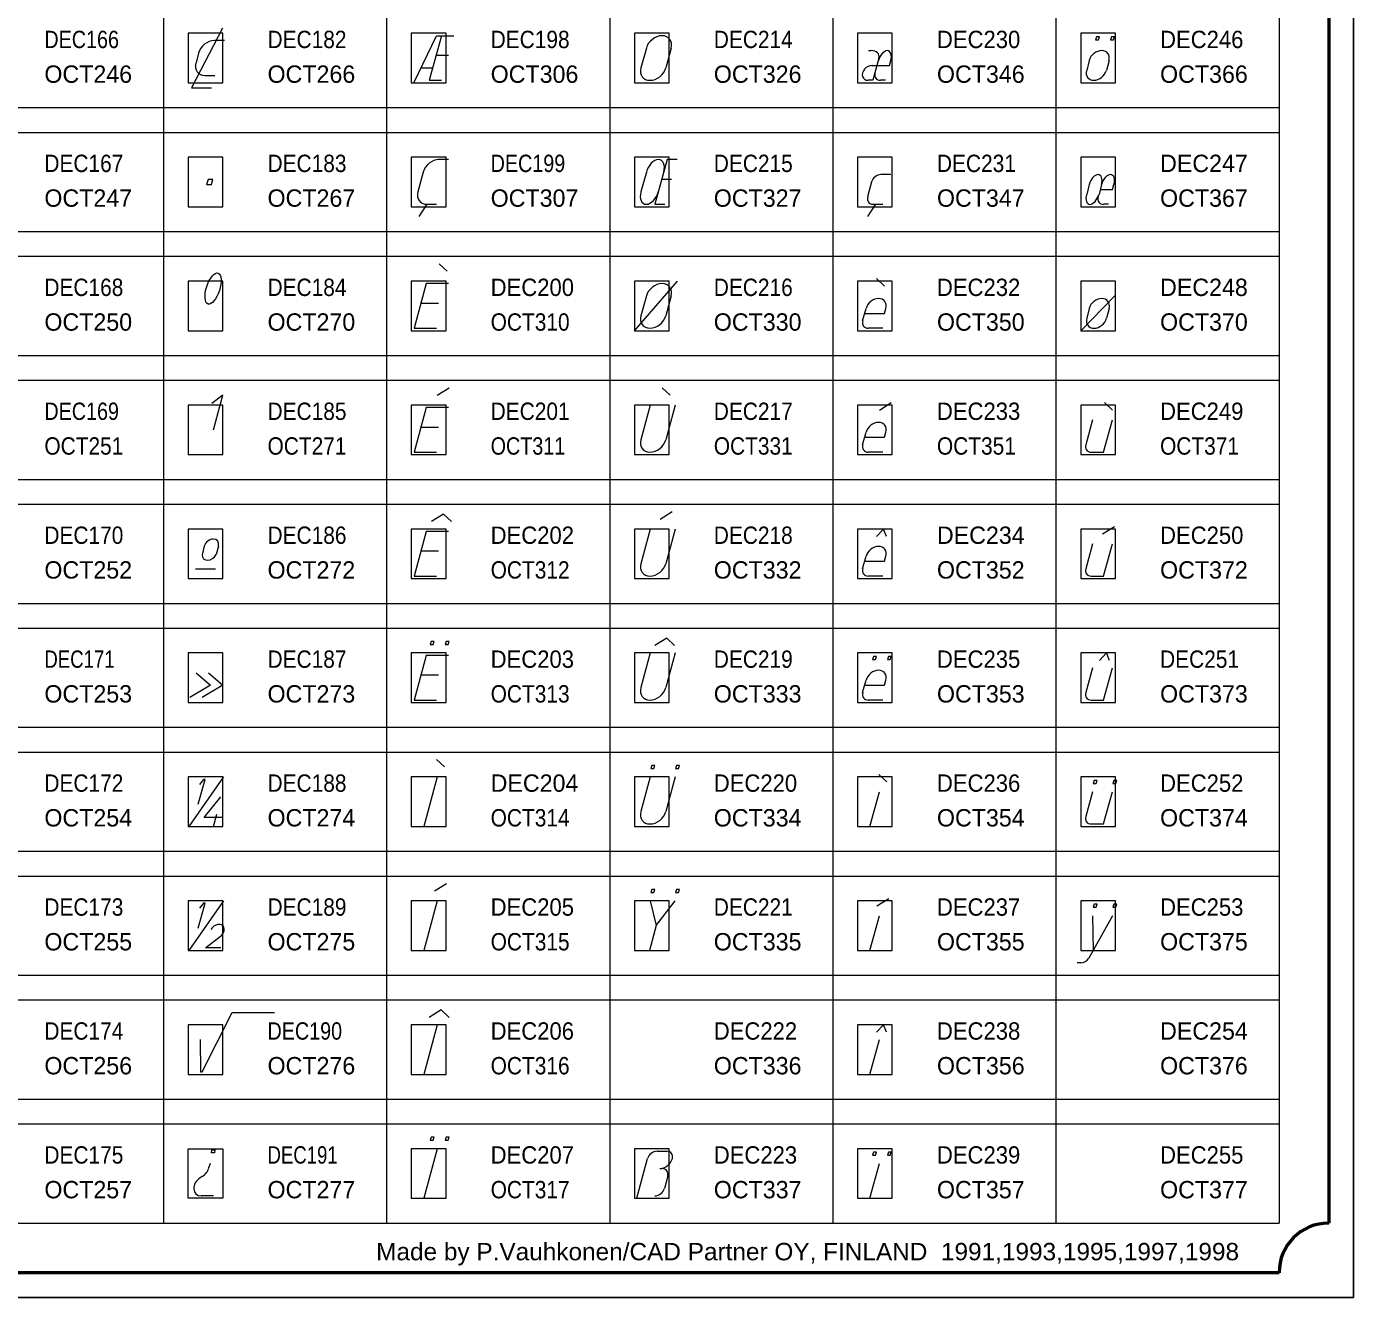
# Model space of a CAD drawing. Extents: x -200 to 7300, y -200 to 4800.
# Drawn here: x 4624 to 7300, y -200 to 2364 of the extents above; entities that cross this region are included whole.
import ezdxf
from ezdxf.enums import TextEntityAlignment as Align

# ---------------------------------------------------------------- set-up
doc = ezdxf.new("R2010")
doc.units = 0
doc.header["$LTSCALE"] = 14
for name, color, linetype, lineweight in [('1', 7, 'Continuous', 13), ('5', 7, 'Continuous', 40), ('6', 7, 'Continuous', 13), ('63', 7, 'Continuous', 13)]:
    doc.layers.add(name, color=color, linetype=linetype, lineweight=lineweight)
doc.layers.add('10', color=7, linetype='Continuous')
doc.layers.add('11', color=7, linetype='Continuous')

msp = doc.modelspace()

# ---------------------------------------------------------------- linework, layer by layer
at = {"layer": '1'}
for p, q in [((5023, 2335), (5003, 2335)), ((4971, 2310), (4966, 2290)), ((5475, 2305), (5450, 2305)), ((5874, 2320), (5863, 2280)), ((5924, 2320), (5913, 2280)), ((6322, 2315), (6327, 2315)), ((5419, 2280), (5443, 2280)), ((6329, 2285), (6339, 2285)), ((6767, 2295), (6762, 2275)), ((6807, 2295), (6802, 2275)), ((4984, 2265), (5004, 2265)), ((6356, 2255), (6346, 2255)), ((5475, 2095), (5455, 2095)), ((5424, 2070), (5413, 2030)), ((5874, 2070), (5863, 2030)), ((6367, 2065), (6347, 2065)), ((5925, 2055), (5905, 2055)), ((6328, 2050), (6320, 2020)), ((6767, 2045), (6762, 2025)), ((6792, 2045), (6787, 2025)), ((5431, 2005), (5415, 1980)), ((5431, 2005), (5451, 2005)), ((6336, 2005), (6320, 1980)), ((6331, 2005), (6351, 2005)), ((6806, 2005), (6796, 2005)), ((5472, 1870), (5456, 1885)), ((5850, 1750), (5937, 1850)), ((6354, 1840), (6338, 1855)), ((5874, 1820), (5863, 1780)), ((5924, 1820), (5913, 1780)), ((6819, 1820), (6750, 1750)), ((5455, 1805), (5420, 1805)), ((6310, 1770), (6317, 1795)), ((6767, 1795), (6762, 1775)), ((6807, 1795), (6802, 1775)), ((6351, 1755), (6321, 1755)), ((5452, 1620), (5476, 1635)), ((5922, 1620), (5906, 1635)), ((5882, 1600), (5863, 1530)), ((5932, 1600), (5913, 1530)), ((6344, 1590), (6368, 1605)), ((6814, 1590), (6798, 1605)), ((5455, 1555), (5420, 1555)), ((6774, 1570), (6760, 1520)), ((6310, 1520), (6317, 1545)), ((6351, 1505), (6321, 1505)), ((5902, 1370), (5926, 1385)), ((5882, 1350), (5863, 1280)), ((5932, 1350), (5913, 1280)), ((6794, 1340), (6818, 1355)), ((4982.5, 1315.4), (4978.2, 1298.2)), ((5011.1, 1315.4), (5006.3, 1298.5)), ((6774, 1320), (6760, 1270)), ((5455, 1305), (5420, 1305)), ((6310, 1270), (6317, 1295)), ((4965, 1270), (5005, 1270)), ((6351, 1255), (6321, 1255)), ((5882, 1100), (5863, 1030)), ((5932, 1100), (5913, 1030)), ((5455, 1055), (5420, 1055)), ((6310, 1020), (6317, 1045)), ((6774, 1070), (6760, 1020)), ((6351, 1005), (6321, 1005)), ((5467, 870), (5451, 885)), ((4952, 750), (5022, 850)), ((5452, 850), (5425, 750)), ((5882, 850), (5863, 780)), ((5932, 850), (5913, 780)), ((6359, 840), (6343, 855)), ((6325, 750), (6344, 820)), ((6774, 820), (6760, 770)), ((5001, 750), (5008, 775)), ((5447, 620), (5471, 635)), ((4952, 500), (5022, 600)), ((5452, 600), (5425, 500)), ((6339, 590), (6363, 605)), ((6325, 500), (6344, 570)), ((6814, 570), (6766.5, 484.5)), ((6774, 570), (6775, 500)), ((5894, 550), (5880, 500)), ((6750, 475), (6743, 475)), ((5452, 350), (5425, 250)), ((6325, 250), (6344, 320)), ((5452, 100), (5425, 0)), ((5896, 95), (5916, 95)), ((4994, 70), (4991, 61)), ((5855, 0), (5876.5, 80)), ((5901.1, 60), (5906.1, 60)), ((6325, 0), (6344, 70)), ((4978, 44), (4974, 41)), ((5917, 45), (5910.4, 20)), ((5001, 5), (4976, 5))]:
    msp.add_line(p, q, dxfattribs=at)
for points in [[(5019, 2360), (4957, 2240), (4997, 2240)], [(5405, 2250), (5451, 2345), (5486, 2345)], [(5461, 2345), (5436, 2255), (5461, 2255)], [(6343, 2300), (6331, 2255), (6321, 2255)], [(6339, 2285), (6364, 2285), (6367, 2295)], [(5936, 2095), (5916, 2095), (5891, 2005), (5911, 2005)], [(6789, 2035), (6814, 2035), (6817, 2045)], [(5475, 1845), (5430, 1845), (5406, 1755), (5451, 1755)], [(6314, 1785), (6354, 1785), (6357, 1795)], [(5001, 1550), (5020, 1620), (4998, 1603)], [(5475, 1595), (5430, 1595), (5406, 1505), (5451, 1505)], [(6771, 1505), (6796, 1505), (6814, 1570)], [(6314, 1535), (6354, 1535), (6357, 1545)], [(5481, 1365), (5465, 1380), (5441, 1365)], [(5475, 1345), (5430, 1345), (5406, 1255), (5451, 1255)], [(6358, 1335), (6352, 1350), (6338, 1335)], [(6771, 1255), (6796, 1255), (6814, 1320)], [(6314, 1285), (6354, 1285), (6357, 1295)], [(5931, 1115), (5915, 1130), (5891, 1115)], [(6808, 1085), (6802, 1100), (6788, 1085)], [(5475, 1095), (5430, 1095), (5406, 1005), (5451, 1005)], [(4966, 1060), (4995, 1035), (4953, 1010)], [(4991, 1060), (5020, 1035), (4978, 1010)], [(6314, 1035), (6354, 1035), (6357, 1045)], [(6771, 1005), (6796, 1005), (6814, 1070)], [(4970, 795), (4984, 845), (4981, 845), (4973, 835)], [(5020, 768), (4982, 768), (5016, 810)], [(6771, 755), (6796, 755), (6814, 820)], [(4970, 545), (4984, 595), (4981, 595), (4973, 585)], [(5882, 600), (5894, 550), (5932, 600)], [(5016, 505), (4985, 505), (5018, 531)], [(4974, 320), (4975, 255), (4978, 255), (5039, 375), (5124, 375)], [(5476, 365), (5460, 380), (5436, 365)], [(6358, 335), (6352, 350), (6338, 335)]]:
    msp.add_lwpolyline(points, dxfattribs=at)
for points in [[(6780, 2337), (6786, 2337), (6788, 2343), (6782, 2343)], [(6810, 2337), (6816, 2337), (6818, 2343), (6812, 2343)], [(4987, 2045), (4997, 2045), (5000, 2055), (4990, 2055)], [(5438, 1117), (5444, 1117), (5446, 1123), (5440, 1123)], [(5468, 1117), (5474, 1117), (5476, 1123), (5470, 1123)], [(6330, 1087), (6336, 1087), (6338, 1093), (6332, 1093)], [(6360, 1087), (6366, 1087), (6368, 1093), (6362, 1093)], [(5883, 867), (5889, 867), (5891, 873), (5885, 873)], [(5933, 867), (5939, 867), (5941, 873), (5935, 873)], [(6775, 837), (6781, 837), (6783, 843), (6777, 843)], [(6815, 837), (6821, 837), (6823, 843), (6817, 843)], [(5883, 617), (5889, 617), (5891, 623), (5885, 623)], [(5933, 617), (5939, 617), (5941, 623), (5935, 623)], [(6775, 587), (6781, 587), (6783, 593), (6777, 593)], [(6815, 587), (6821, 587), (6823, 593), (6817, 593)], [(5438, 117), (5444, 117), (5446, 123), (5440, 123)], [(5468, 117), (5474, 117), (5476, 123), (5470, 123)], [(5003, 92), (4997, 92), (4998, 98), (5004, 98)], [(6330, 87), (6336, 87), (6338, 93), (6332, 93)], [(6360, 87), (6366, 87), (6368, 93), (6362, 93)]]:
    msp.add_lwpolyline(points, close=True, dxfattribs=at)
for centre, major_axis, ratio, start_param, end_param in [((4995.99, 2310), (-21.5, -18.81), 0.765566, 3.860429, 5.4312252), ((5899, 2320), (-21.5, -18.81), 0.765566, 2.2896326, 5.4312252), ((6323, 2300), (20.01, 5.84), 0.690505, 5.8830717, 7.453868), ((6354.45, 2294.85), (-8.15, -19.47), 0.561107, 1.8015141, 4.9431067), ((6786.99, 2295), (-17.2, -15.05), 0.765566, 2.2896326, 5.4312252), ((4990.63, 2290), (21.5, 18.81), 0.765566, 2.2896328, 3.860429), ((5888, 2280), (21.5, 18.81), 0.765566, 2.2896328, 5.4312254), ((6325.08, 2270), (-12.94, -11.3), 0.762607, 3.8593293, 7.000922), ((6781.63, 2275), (17.2, 15.05), 0.765566, 2.2896328, 5.4312254), ((6350.08, 2270), (-12.94, -11.3), 0.762607, 5.4301255, 7.0009218), ((5449, 2070), (-21.5, -18.81), 0.765566, 3.860429, 5.4312252), ((5891.5, 2070), (-11.5, -23.96), 0.619201, 1.8595695, 5.0011621), ((6343, 2050), (-12.9, -11.29), 0.765566, 3.860429, 5.4312252), ((6779.46, 2044.85), (-8.15, -19.47), 0.561107, 1.8015142, 4.9431068), ((6804.46, 2044.85), (-8.15, -19.47), 0.561107, 1.8015142, 4.9431068), ((5437.97, 2030), (21.5, 18.81), 0.765566, 2.2896328, 3.860429), ((5880.5, 2030), (-11.5, -23.96), 0.619201, 5.001162, 8.1427546), ((6335.3, 2020), (12.9, 11.29), 0.765566, 2.2896328, 3.860429), ((6774.02, 2024.85), (-8.15, -19.47), 0.561107, 4.9431069, 8.0846995), ((6800.16, 2019.85), (12.94, 11.3), 0.762607, 2.2885332, 3.8593294), ((5899, 1820), (-21.5, -18.81), 0.765566, 2.2896326, 5.4312252), ((6337.02, 1795), (-17.2, -15.05), 0.765566, 2.2896326, 5.4312252), ((6787.02, 1795), (-17.2, -15.05), 0.765566, 2.2896326, 5.4312252), ((5888, 1780), (21.5, 18.81), 0.765566, 2.2896328, 5.4312254), ((6325.32, 1770), (12.9, 11.29), 0.765566, 2.2896328, 3.860429), ((6782, 1775), (17.2, 15.05), 0.765566, 2.2896328, 5.4312254), ((6337.03, 1545), (-17.2, -15.05), 0.765566, 2.2896326, 5.4312252), ((5888, 1530), (21.5, 18.81), 0.765566, 2.2896328, 5.4312254), ((6325.33, 1520), (12.9, 11.29), 0.765566, 2.2896328, 3.860429), ((6775, 1520), (12.9, 11.29), 0.765566, 2.2896328, 3.860429), ((4996.79, 1315.43), (-12.29, -10.75), 0.765566, 2.2896326, 5.4312252), ((6337.05, 1295), (-17.2, -15.05), 0.765566, 2.2896326, 5.4312252), ((4992.96, 1301.14), (12.29, 10.75), 0.765566, 2.4993147, 5.2422622), ((5888.02, 1280), (21.5, 18.81), 0.765566, 2.2896328, 5.4312254), ((6325.35, 1270), (12.9, 11.29), 0.765566, 2.2896328, 3.860429), ((6775, 1270), (12.9, 11.29), 0.765566, 2.2896328, 3.860429), ((6337.06, 1045), (-17.2, -15.05), 0.765566, 2.2896326, 5.4312252), ((5888.04, 1030), (21.5, 18.81), 0.765566, 2.2896328, 5.4312254), ((6325.36, 1020), (12.9, 11.29), 0.765566, 2.2896328, 3.860429), ((6775, 1020), (12.9, 11.29), 0.765566, 2.2896328, 3.860429), ((5888.05, 780), (21.5, 18.81), 0.765566, 2.2896328, 5.4312254), ((6775, 770), (12.9, 11.29), 0.765566, 2.2896328, 3.860429), ((5008.31, 538.61), (-12.07, -10.55), 0.762607, 1.7142283, 5.1851471), ((6754.02, 490), (12.9, 11.29), 0.765566, 3.8604291, 5.0573215), ((5891.5, 80), (-12.9, -11.29), 0.765566, 3.860429, 5.4312252), ((5911.5, 80), (-12.9, -11.29), 0.765566, 2.2896326, 3.8604289), ((4971.32, 60.7), (17.2, 15.05), 0.765566, 4.4484316, 5.4312253), ((5906.5, 80), (17.2, 15.05), 0.765566, 3.860429, 5.4312252), ((5902.12, 45), (-12.9, -11.29), 0.765566, 2.2896326, 3.864226), ((4981.75, 25), (17.2, 15.05), 0.765566, 1.3623375, 3.860429), ((5895.42, 20), (-12.9, -11.29), 0.765566, 0.7188363, 2.2896326)]:
    msp.add_ellipse(centre, major_axis=major_axis, ratio=ratio, start_param=start_param, end_param=end_param, dxfattribs=at)
msp.add_ellipse((5000.22, 1835), major_axis=(10.22, 31.22), ratio=0.408607, dxfattribs=at)
at = {"layer": '5', "lineweight": 53}
for p, q in [((7250, 4650), (7250, -50)), ((7150, -150), (-50, -150))]:
    msp.add_line(p, q, dxfattribs=at)
at = {"layer": '5', "lineweight": 25}
msp.add_lwpolyline([(-200, -200), (-200, 4800), (7300, 4800), (7300, -200)], close=True, dxfattribs=at)
at = {"layer": '5', "lineweight": 53}
msp.add_arc((7250, -150), 100, 90, 179.99999, dxfattribs=at)
at = {"layer": '6'}
for p, q in [((4900, 3950), (4900, -50)), ((5350, 3950), (5350, -50)), ((5800, 3950), (5800, -50)), ((6250, 3950), (6250, -50)), ((6700, 3950), (6700, -50)), ((7150, 3950), (7150, -50)), ((-50, 2200), (7150, 2200)), ((-50, 2150), (7150, 2150)), ((-50, 1950), (7150, 1950)), ((-50, 1900), (7150, 1900)), ((-50, 1700), (7150, 1700)), ((-50, 1650), (7150, 1650)), ((-50, 1450), (7150, 1450)), ((-50, 1400), (7150, 1400)), ((-50, 1200), (7150, 1200)), ((-50, 1150), (7150, 1150)), ((-50, 950), (7150, 950)), ((-50, 900), (7150, 900)), ((-50, 700), (7150, 700)), ((-50, 650), (7150, 650)), ((-50, 450), (7150, 450)), ((-50, 400), (7150, 400)), ((-50, 200), (7150, 200)), ((-50, 150), (7150, 150)), ((-50, -50), (7150, -50))]:
    msp.add_line(p, q, dxfattribs=at)
at = {"layer": '63'}
for points in [[(4950, 2250), (5020, 2250), (5020, 2350), (4950, 2350)], [(5400, 2250), (5470, 2250), (5470, 2350), (5400, 2350)], [(5850, 2250), (5920, 2250), (5920, 2350), (5850, 2350)], [(6300, 2250), (6370, 2250), (6370, 2350), (6300, 2350)], [(6750, 2250), (6820, 2250), (6820, 2350), (6750, 2350)], [(4950, 2000), (5020, 2000), (5020, 2100), (4950, 2100)], [(5400, 2000), (5470, 2000), (5470, 2100), (5400, 2100)], [(5850, 2000), (5920, 2000), (5920, 2100), (5850, 2100)], [(6300, 2000), (6370, 2000), (6370, 2100), (6300, 2100)], [(6750, 2000), (6820, 2000), (6820, 2100), (6750, 2100)], [(4950, 1750), (5020, 1750), (5020, 1850), (4950, 1850)], [(5400, 1750), (5470, 1750), (5470, 1850), (5400, 1850)], [(5850, 1750), (5920, 1750), (5920, 1850), (5850, 1850)], [(6300, 1750), (6370, 1750), (6370, 1850), (6300, 1850)], [(6750, 1750), (6820, 1750), (6820, 1850), (6750, 1850)], [(4950, 1500), (5020, 1500), (5020, 1600), (4950, 1600)], [(5400, 1500), (5470, 1500), (5470, 1600), (5400, 1600)], [(5850, 1500), (5920, 1500), (5920, 1600), (5850, 1600)], [(6300, 1500), (6370, 1500), (6370, 1600), (6300, 1600)], [(6750, 1500), (6820, 1500), (6820, 1600), (6750, 1600)], [(4950, 1250), (5020, 1250), (5020, 1350), (4950, 1350)], [(5400, 1250), (5470, 1250), (5470, 1350), (5400, 1350)], [(5850, 1250), (5920, 1250), (5920, 1350), (5850, 1350)], [(6300, 1250), (6370, 1250), (6370, 1350), (6300, 1350)], [(6750, 1250), (6820, 1250), (6820, 1350), (6750, 1350)], [(4950, 1000), (5020, 1000), (5020, 1100), (4950, 1100)], [(5400, 1000), (5470, 1000), (5470, 1100), (5400, 1100)], [(5850, 1000), (5920, 1000), (5920, 1100), (5850, 1100)], [(6300, 1000), (6370, 1000), (6370, 1100), (6300, 1100)], [(6750, 1000), (6820, 1000), (6820, 1100), (6750, 1100)], [(4950, 750), (5020, 750), (5020, 850), (4950, 850)], [(5400, 750), (5470, 750), (5470, 850), (5400, 850)], [(5850, 750), (5920, 750), (5920, 850), (5850, 850)], [(6300, 750), (6370, 750), (6370, 850), (6300, 850)], [(6750, 750), (6820, 750), (6820, 850), (6750, 850)], [(4950, 500), (5020, 500), (5020, 600), (4950, 600)], [(5400, 500), (5470, 500), (5470, 600), (5400, 600)], [(5850, 500), (5920, 500), (5920, 600), (5850, 600)], [(6300, 500), (6370, 500), (6370, 600), (6300, 600)], [(6750, 500), (6820, 500), (6820, 600), (6750, 600)], [(4950, 250), (5020, 250), (5020, 350), (4950, 350)], [(5400, 250), (5470, 250), (5470, 350), (5400, 350)], [(6300, 250), (6370, 250), (6370, 350), (6300, 350)], [(4950, 100), (5020, 100), (5020, 0), (4950, 0)], [(5400, 0), (5470, 0), (5470, 100), (5400, 100)], [(5850, 0), (5920, 0), (5920, 100), (5850, 100)], [(6300, 0), (6370, 0), (6370, 100), (6300, 100)]]:
    msp.add_lwpolyline(points, close=True, dxfattribs=at)

# ---------------------------------------------------------------- texts
at = {"layer": '10'}
for s, width, p in [('DEC166', 0.85, (4660, 2320)), ('DEC182', 0.9, (5110, 2320)), ('DEC198', 0.9, (5560, 2320)), ('DEC214', 0.9, (6010, 2320)), ('DEC230', 0.95, (6460, 2320)), ('DEC246', 0.95, (6910, 2320)), ('DEC167', 0.9, (4660, 2070)), ('DEC183', 0.9, (5110, 2070)), ('DEC199', 0.85, (5560, 2070)), ('DEC215', 0.9, (6010, 2070)), ('DEC231', 0.9, (6460, 2070)), ('DEC168', 0.9, (4660, 1820)), ('DEC184', 0.9, (5110, 1820)), ('DEC200', 0.95, (5560, 1820)), ('DEC216', 0.9, (6010, 1820)), ('DEC232', 0.95, (6460, 1820)), ('DEC169', 0.85, (4660, 1570)), ('DEC185', 0.9, (5110, 1570)), ('DEC201', 0.9, (5560, 1570)), ('DEC217', 0.9, (6010, 1570)), ('DEC233', 0.95, (6460, 1570)), ('DEC249', 0.95, (6910, 1570)), ('DEC170', 0.9, (4660, 1320)), ('DEC186', 0.9, (5110, 1320)), ('DEC202', 0.95, (5560, 1320)), ('DEC218', 0.9, (6010, 1320)), ('DEC250', 0.95, (6910, 1320)), ('DEC171', 0.8, (4660, 1070)), ('DEC187', 0.9, (5110, 1070)), ('DEC203', 0.95, (5560, 1070)), ('DEC219', 0.9, (6010, 1070)), ('DEC235', 0.95, (6460, 1070)), ('DEC251', 0.9, (6910, 1070)), ('DEC172', 0.9, (4660, 820)), ('DEC188', 0.9, (5110, 820)), ('DEC220', 0.95, (6010, 820)), ('DEC236', 0.95, (6460, 820)), ('DEC252', 0.95, (6910, 820)), ('DEC173', 0.9, (4660, 570)), ('DEC189', 0.9, (5110, 570)), ('DEC205', 0.95, (5560, 570)), ('DEC221', 0.9, (6010, 570)), ('DEC237', 0.95, (6460, 570)), ('DEC253', 0.95, (6910, 570)), ('DEC174', 0.9, (4660, 320)), ('DEC190', 0.85, (5110, 320)), ('DEC206', 0.95, (5560, 320)), ('DEC222', 0.95, (6010, 320)), ('DEC238', 0.95, (6460, 320)), ('DEC175', 0.9, (4660, 70)), ('DEC191', 0.8, (5110, 70)), ('DEC207', 0.95, (5560, 70)), ('DEC223', 0.95, (6010, 70)), ('DEC239', 0.95, (6460, 70)), ('DEC255', 0.95, (6910, 70))]:
    msp.add_text(s, height=35, dxfattribs=dict(at, width=width)).set_placement(p)
for s, p in [('DEC247', (6910, 2070)), ('DEC248', (6910, 1820)), ('DEC234', (6460, 1320)), ('DEC204', (5560, 820)), ('DEC254', (6910, 320))]:
    msp.add_text(s, height=35, dxfattribs=at).set_placement(p)
at = {"layer": '11'}
for s, p in [('OCT246', (4660, 2250)), ('OCT266', (5110, 2250)), ('OCT306', (5560, 2250)), ('OCT326', (6010, 2250)), ('OCT346', (6460, 2250)), ('OCT366', (6910, 2250)), ('OCT247', (4660, 2000)), ('OCT267', (5110, 2000)), ('OCT307', (5560, 2000)), ('OCT327', (6010, 2000)), ('OCT347', (6460, 2000)), ('OCT367', (6910, 2000)), ('OCT250', (4660, 1750)), ('OCT270', (5110, 1750)), ('OCT330', (6010, 1750)), ('OCT350', (6460, 1750)), ('OCT370', (6910, 1750)), ('OCT252', (4660, 1250)), ('OCT272', (5110, 1250)), ('OCT332', (6010, 1250)), ('OCT352', (6460, 1250)), ('OCT372', (6910, 1250)), ('OCT253', (4660, 1000)), ('OCT273', (5110, 1000)), ('OCT333', (6010, 1000)), ('OCT353', (6460, 1000)), ('OCT373', (6910, 1000)), ('OCT254', (4660, 750)), ('OCT274', (5110, 750)), ('OCT334', (6010, 750)), ('OCT354', (6460, 750)), ('OCT374', (6910, 750)), ('OCT255', (4660, 500)), ('OCT275', (5110, 500)), ('OCT335', (6010, 500)), ('OCT355', (6460, 500)), ('OCT375', (6910, 500)), ('OCT256', (4660, 250)), ('OCT276', (5110, 250)), ('OCT336', (6010, 250)), ('OCT356', (6460, 250)), ('OCT376', (6910, 250)), ('OCT257', (4660, 0)), ('OCT277', (5110, 0)), ('OCT337', (6010, 0)), ('OCT357', (6460, 0)), ('OCT377', (6910, 0))]:
    msp.add_text(s, height=35, dxfattribs=at).set_placement(p)
for s, width, p in [('OCT310', 0.9, (5560, 1750)), ('OCT251', 0.9, (4660, 1500)), ('OCT271', 0.9, (5110, 1500)), ('OCT311', 0.85, (5560, 1500)), ('OCT331', 0.9, (6010, 1500)), ('OCT351', 0.9, (6460, 1500)), ('OCT371', 0.9, (6910, 1500)), ('OCT312', 0.9, (5560, 1250)), ('OCT313', 0.9, (5560, 1000)), ('OCT314', 0.9, (5560, 750)), ('OCT315', 0.9, (5560, 500)), ('OCT316', 0.9, (5560, 250)), ('OCT317', 0.9, (5560, 0))]:
    msp.add_text(s, height=35, dxfattribs=dict(at, width=width)).set_placement(p)
at = {"layer": '5', "width": 1.05}
msp.add_text('Made by P.Vauhkonen/CAD Partner OY, FINLAND  1991,1993,1995,1997,1998', height=35, dxfattribs=at).set_placement((7069.3, -125), align=Align.RIGHT)

doc.saveas('drawing.dxf')
